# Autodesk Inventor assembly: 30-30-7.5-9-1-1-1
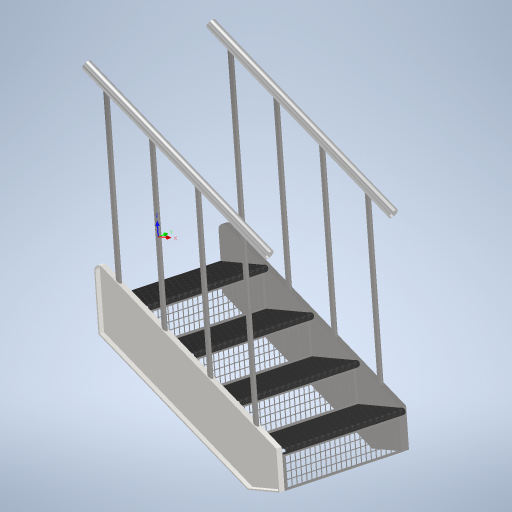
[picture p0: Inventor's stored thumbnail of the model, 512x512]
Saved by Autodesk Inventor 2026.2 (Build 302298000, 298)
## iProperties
RuleStatus: InUse
Company: Elevation Stair Company
Created: 2022-06
Part Number: 30-30-7.5-9-1-1-1
Document SubType Name: Assembly
Designer: David Reaume
Description: Metal Stairs
AfterAnyUserParamChange0: Type Name
Run: 9.000 in
TheAngle: 39.81 deg
TargetRise: 7.250 in
Rise: 7.500 in
Height: 30.000 in
Width: 30.000 in
StringerWidth: 10.000 in
StringerThickness: 1.500 in
StringerLength: 46.861 in
NumberOfSteps: 5.000 ul
Length: 36.000 in
TreadThickness: 1.250 in
StringerStockLength: 48.000 in
RailingStockLength: 46.861 in
RailingWidth: 3.000 in
RailingThickness: 2.000 in
RightRail: True
LeftRail: True
StringerMaterial: Steel, Galvanized
TreadMaterial: Steel, Wrought
RiserMaterial: Steel, Galvanized
BalusterMaterial: Steel, Galvanized
HandrailMaterial: Aluminum 6061
HasHandrail: True
HasRiser: True
BalusterLength: 36.000 in
BalusterDia: 1.000 in
INDDataset: sample
Author: David Reaume
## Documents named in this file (13)
- C:\Users\MichelleRasmussen\OneDrive\Documents\AutodeskTraining\Autodesk\Informed Design\Staircase Sample1\Staircase Sample\Staircase Sample.iam
- C:\Users\MichelleRasmussen\OneDrive\Documents\AutodeskTraining\Autodesk\Informed Design\Staircase Sample1\Staircase Sample\Stringer.ipt
- C:\Users\MichelleRasmussen\OneDrive\Documents\AutodeskTraining\Autodesk\Informed Design\Staircase Sample1\Staircase Sample\Tread.ipt
- C:\Users\MichelleRasmussen\OneDrive\Documents\AutodeskTraining\Autodesk\Informed Design\Staircase Sample1\Staircase Sample\Riser.ipt
- C:\Users\MichelleRasmussen\OneDrive\Documents\AutodeskTraining\Autodesk\Informed Design\Staircase Sample1\Staircase Sample\Baluster.ipt
- C:\Users\MichelleRasmussen\OneDrive\Documents\AutodeskTraining\Autodesk\Informed Design\Staircase Sample1\Staircase Sample\Railing.ipt
- C:\Users\MichelleRasmussen\OneDrive\Documents\AutodeskTraining\Autodesk\Informed Design\Staircase Sample1\Staircase Sample\Left Stringer_MIR.ipt
- D:\MID Staircase\Stringer.ipt
- D:\MID Staircase\Tread.ipt
- D:\MID Staircase\Riser.ipt
- D:\MID Staircase\Baluster.ipt
- D:\MID Staircase\Railing.ipt
- D:\MID Staircase\Left Stringer_MIR.ipt
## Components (20 placed, 7 different names)
1. Stringer
2. Left Stringer_MIR:1
3. Right Railing
4. Left Railing — Flush:7, Flush:8, Flush:9
5. Tread:1
6. Tread:2
7. Tread:3
8. Tread:4
9. Riser:1
10. Riser:2
11. Riser:3
12. Riser:4
13. Baluster:1
14. Baluster:12
15. Baluster:15
16. Baluster:17
17. Baluster:7 — Flush:11, Flush:12
18. Baluster:8
19. Baluster:13
20. Baluster:16
## Component patterns: Tread Pattern (4 elements), Riser Pattern (4 elements), Right Baluster Pattern (4 elements), Left Baluster Pattern (4 elements)
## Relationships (5: Flush 5)
- Flush:7: Left Railing
- Flush:8: Left Railing
- Flush:9: Left Railing
- Flush:11: Baluster:7
- Flush:12: Baluster:7
## Named parameters: TheAngle = 6.94738 mm, StringerThickness = 38.1 mm, StringerLength = 1190.28205 mm, Length = 914.4 mm, TheAngleRounded = 6.94816 mm, StringerStockLength = 1219.2 mm, DiagonalTreadSpacing = 297.57051 mm, BalusterDia = 25.4 mm, BalusterLength = 914.4 mm, RailingStockLength = 1190.28205 mm, RailingWidth = 76.2 mm, RailingThickness = 50.8 mm, StringerSpacing = 876.3 mm
